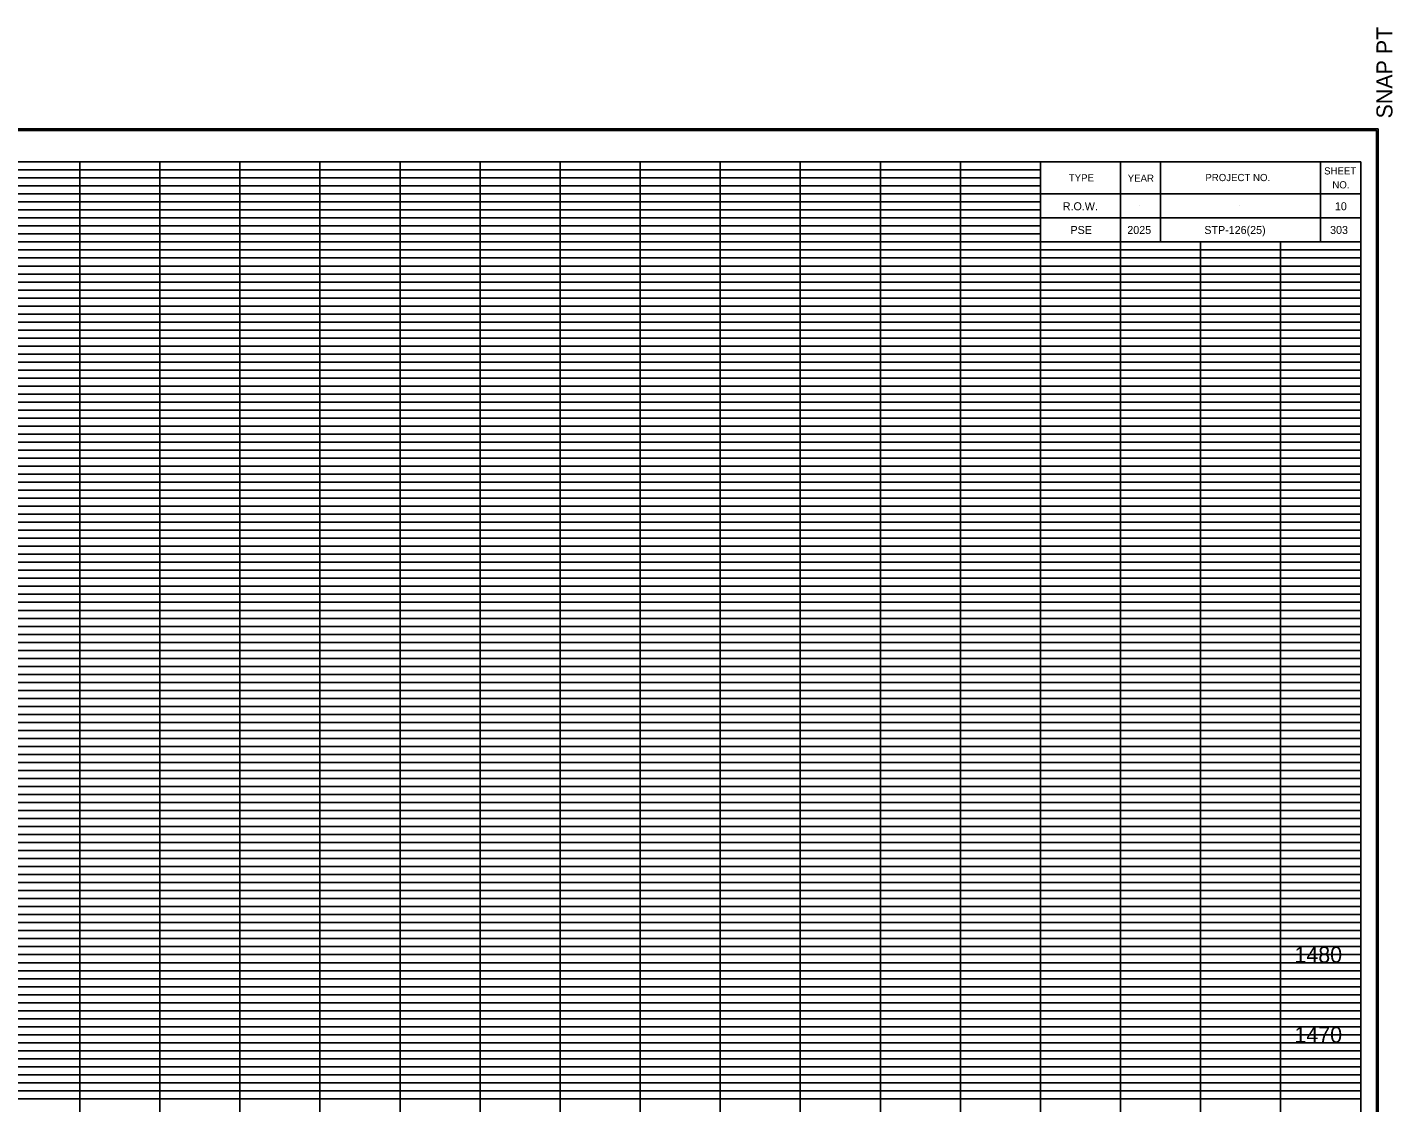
# Model space of a CAD drawing. Extents: x 980 to 2064, y 978 to 2267.
# Drawn here: x 1523.4 to 1694, y 2132.5 to 2266.8 of the extents above; entities that cross this region are included whole.
import ezdxf

# ---------------------------------------------------------------- set-up
doc = ezdxf.new("R2010")
doc.units = 0
for name, color, linetype in [('Default', 7, 'Continuous'), ('DESIGN - SCRATCH - User 1', 7, 'Continuous'), ('DESIGN - SHEET - Corner Text', 7, 'Continuous'), ('DESIGN - SHEET - Light Grid', 7, 'Continuous'), ('DESIGN - SHEET - Linework', 7, 'Continuous'), ('DESIGN - SHEET - Plot Shape', 7, 'Continuous')]:
    doc.layers.add(name, color=color, linetype=linetype)

# ---------------------------------------------------------------- blocks, each defined once
blk = doc.blocks.new('XSTSHT')
at = {"layer": 'DESIGN - SCRATCH - User 1'}
for p, q in [((28.5, 20.45), (28.5, 20.45)), ((29.24, 20.45), (29.24, 20.45)), ((30.49, 20.45), (30.49, 20.45)), ((31.74, 20.45), (31.74, 20.45)), ((28.5, 20.15), (28.5, 20.15)), ((29.24, 20.15), (29.24, 20.15)), ((30.49, 20.15), (30.49, 20.15)), ((31.74, 20.15), (31.74, 20.15))]:
    blk.add_line(p, q, dxfattribs=at)
at = {"layer": 'DESIGN - SHEET - Light Grid'}
for p, q in [((8, 20.9), (16, 20.9)), ((16, 20.9), (24, 20.9)), ((24, 20.9), (28, 20.9)), ((8, 20.8), (16, 20.8)), ((8, 20.7), (16, 20.7)), ((16, 20.8), (24, 20.8)), ((16, 20.7), (24, 20.7)), ((24, 20.8), (28, 20.8)), ((24, 20.7), (28, 20.7)), ((8, 20.6), (16, 20.6)), ((8, 20.5), (16, 20.5)), ((16, 20.6), (24, 20.6)), ((16, 20.5), (24, 20.5)), ((24, 20.6), (28, 20.6)), ((24, 20.5), (28, 20.5)), ((8, 20.4), (16, 20.4)), ((8, 20.3), (16, 20.3)), ((16, 20.4), (24, 20.4)), ((16, 20.3), (24, 20.3)), ((24, 20.4), (28, 20.4)), ((24, 20.3), (28, 20.3)), ((8, 20.2), (16, 20.2)), ((16, 20.2), (24, 20.2)), ((24, 20.2), (28, 20.2)), ((8, 20.1), (16, 20.1)), ((16, 20.1), (24, 20.1)), ((24, 20.1), (28, 20.1)), ((8, 19.9), (16, 19.9)), ((8, 19.8), (16, 19.8)), ((16, 19.9), (24, 19.9)), ((16, 19.8), (24, 19.8)), ((24, 19.9), (32, 19.9)), ((24, 19.8), (32, 19.8)), ((8, 19.7), (16, 19.7)), ((16, 19.7), (24, 19.7)), ((24, 19.7), (32, 19.7)), ((8, 19.6), (16, 19.6)), ((8, 19.5), (16, 19.5)), ((16, 19.6), (24, 19.6)), ((16, 19.5), (24, 19.5)), ((24, 19.6), (32, 19.6)), ((24, 19.5), (32, 19.5)), ((8, 19.4), (16, 19.4)), ((8, 19.3), (16, 19.3)), ((16, 19.4), (24, 19.4)), ((16, 19.3), (24, 19.3)), ((24, 19.4), (32, 19.4)), ((24, 19.3), (32, 19.3)), ((8, 19.2), (16, 19.2)), ((16, 19.2), (24, 19.2)), ((24, 19.2), (32, 19.2)), ((8, 19.1), (16, 19.1)), ((16, 19.1), (24, 19.1)), ((24, 19.1), (32, 19.1)), ((8, 18.9), (16, 18.9)), ((8, 18.8), (16, 18.8)), ((16, 18.9), (24, 18.9)), ((16, 18.8), (24, 18.8)), ((24, 18.9), (32, 18.9)), ((24, 18.8), (32, 18.8)), ((8, 18.7), (16, 18.7)), ((8, 18.6), (16, 18.6)), ((16, 18.7), (24, 18.7)), ((16, 18.6), (24, 18.6)), ((24, 18.7), (32, 18.7)), ((24, 18.6), (32, 18.6)), ((8, 18.5), (16, 18.5)), ((16, 18.5), (24, 18.5)), ((24, 18.5), (32, 18.5)), ((8, 18.4), (16, 18.4)), ((8, 18.3), (16, 18.3)), ((16, 18.4), (24, 18.4)), ((16, 18.3), (24, 18.3)), ((24, 18.4), (32, 18.4)), ((24, 18.3), (32, 18.3)), ((8, 18.2), (16, 18.2)), ((8, 18.1), (16, 18.1)), ((16, 18.2), (24, 18.2)), ((16, 18.1), (24, 18.1)), ((24, 18.2), (32, 18.2)), ((24, 18.1), (32, 18.1)), ((8, 17.9), (16, 17.9)), ((8, 17.8), (16, 17.8)), ((16, 17.9), (24, 17.9)), ((16, 17.8), (24, 17.8)), ((24, 17.9), (32, 17.9)), ((24, 17.8), (32, 17.8)), ((8, 17.7), (16, 17.7)), ((8, 17.6), (16, 17.6)), ((16, 17.7), (24, 17.7)), ((16, 17.6), (24, 17.6)), ((24, 17.7), (32, 17.7)), ((24, 17.6), (32, 17.6)), ((8, 17.5), (16, 17.5)), ((8, 17.4), (16, 17.4)), ((16, 17.5), (24, 17.5)), ((16, 17.4), (24, 17.4)), ((24, 17.5), (32, 17.5)), ((24, 17.4), (32, 17.4)), ((8, 17.3), (16, 17.3)), ((16, 17.3), (24, 17.3)), ((24, 17.3), (32, 17.3)), ((8, 17.2), (16, 17.2)), ((8, 17.1), (16, 17.1)), ((16, 17.2), (24, 17.2)), ((16, 17.1), (24, 17.1)), ((24, 17.2), (32, 17.2)), ((24, 17.1), (32, 17.1)), ((8, 16.9), (16, 16.9)), ((16, 16.9), (24, 16.9)), ((24, 16.9), (32, 16.9)), ((8, 16.8), (16, 16.8)), ((16, 16.8), (24, 16.8)), ((24, 16.8), (32, 16.8)), ((8, 16.7), (16, 16.7)), ((8, 16.6), (16, 16.6)), ((16, 16.7), (24, 16.7)), ((16, 16.6), (24, 16.6)), ((24, 16.7), (32, 16.7)), ((24, 16.6), (32, 16.6)), ((8, 16.5), (16, 16.5)), ((8, 16.4), (16, 16.4)), ((16, 16.5), (24, 16.5)), ((16, 16.4), (24, 16.4)), ((24, 16.5), (32, 16.5)), ((24, 16.4), (32, 16.4)), ((8, 16.3), (16, 16.3)), ((16, 16.3), (24, 16.3)), ((24, 16.3), (32, 16.3)), ((8, 16.2), (16, 16.2)), ((8, 16.1), (16, 16.1)), ((16, 16.2), (24, 16.2)), ((16, 16.1), (24, 16.1)), ((24, 16.2), (32, 16.2)), ((24, 16.1), (32, 16.1)), ((8, 15.9), (16, 15.9)), ((16, 15.9), (24, 15.9)), ((24, 15.9), (32, 15.9)), ((8, 15.8), (16, 15.8)), ((8, 15.7), (16, 15.7)), ((16, 15.8), (24, 15.8)), ((16, 15.7), (24, 15.7)), ((24, 15.8), (32, 15.8)), ((24, 15.7), (32, 15.7)), ((8, 15.6), (16, 15.6)), ((16, 15.6), (24, 15.6)), ((24, 15.6), (32, 15.6)), ((8, 15.5), (16, 15.5)), ((8, 15.4), (16, 15.4)), ((16, 15.5), (24, 15.5)), ((16, 15.4), (24, 15.4)), ((24, 15.5), (32, 15.5)), ((24, 15.4), (32, 15.4)), ((8, 15.3), (16, 15.3)), ((8, 15.2), (16, 15.2)), ((16, 15.3), (24, 15.3)), ((16, 15.2), (24, 15.2)), ((24, 15.3), (32, 15.3)), ((24, 15.2), (32, 15.2)), ((8, 15.1), (16, 15.1)), ((16, 15.1), (24, 15.1)), ((24, 15.1), (32, 15.1)), ((8, 14.9), (16, 14.9)), ((16, 14.9), (24, 14.9)), ((24, 14.9), (32, 14.9)), ((8, 14.8), (16, 14.8)), ((8, 14.7), (16, 14.7)), ((16, 14.8), (24, 14.8)), ((16, 14.7), (24, 14.7)), ((24, 14.8), (32, 14.8)), ((24, 14.7), (32, 14.7)), ((8, 14.6), (16, 14.6)), ((8, 14.5), (16, 14.5)), ((16, 14.6), (24, 14.6)), ((16, 14.5), (24, 14.5)), ((24, 14.6), (32, 14.6)), ((24, 14.5), (32, 14.5)), ((8, 14.4), (16, 14.4)), ((16, 14.4), (24, 14.4)), ((24, 14.4), (32, 14.4)), ((8, 14.3), (16, 14.3)), ((8, 14.2), (16, 14.2)), ((16, 14.3), (24, 14.3)), ((16, 14.2), (24, 14.2)), ((24, 14.3), (32, 14.3)), ((24, 14.2), (32, 14.2)), ((8, 14.1), (16, 14.1)), ((16, 14.1), (24, 14.1)), ((24, 14.1), (32, 14.1)), ((8, 13.9), (16, 13.9)), ((16, 13.9), (24, 13.9)), ((24, 13.9), (32, 13.9)), ((8, 13.8), (16, 13.8)), ((8, 13.7), (16, 13.7)), ((16, 13.8), (24, 13.8)), ((16, 13.7), (24, 13.7)), ((24, 13.8), (32, 13.8)), ((24, 13.7), (32, 13.7)), ((8, 13.6), (16, 13.6)), ((8, 13.5), (16, 13.5)), ((16, 13.6), (24, 13.6)), ((16, 13.5), (24, 13.5)), ((24, 13.6), (32, 13.6)), ((24, 13.5), (32, 13.5)), ((8, 13.4), (16, 13.4)), ((16, 13.4), (24, 13.4)), ((24, 13.4), (32, 13.4)), ((8, 13.3), (16, 13.3)), ((8, 13.2), (16, 13.2)), ((16, 13.3), (24, 13.3)), ((16, 13.2), (24, 13.2)), ((24, 13.3), (32, 13.3)), ((24, 13.2), (32, 13.2)), ((8, 13.1), (16, 13.1)), ((16, 13.1), (24, 13.1)), ((24, 13.1), (32, 13.1)), ((8, 12.9), (16, 12.9)), ((8, 12.8), (16, 12.8)), ((16, 12.9), (24, 12.9)), ((16, 12.8), (24, 12.8)), ((24, 12.9), (32, 12.9)), ((24, 12.8), (32, 12.8)), ((8, 12.7), (16, 12.7)), ((16, 12.7), (24, 12.7)), ((24, 12.7), (32, 12.7)), ((8, 12.6), (16, 12.6)), ((8, 12.5), (16, 12.5)), ((16, 12.6), (24, 12.6)), ((16, 12.5), (24, 12.5)), ((24, 12.6), (32, 12.6)), ((24, 12.5), (32, 12.5)), ((8, 12.4), (16, 12.4)), ((8, 12.3), (16, 12.3)), ((16, 12.4), (24, 12.4)), ((16, 12.3), (24, 12.3)), ((24, 12.4), (32, 12.4)), ((24, 12.3), (32, 12.3)), ((8, 12.2), (16, 12.2)), ((16, 12.2), (24, 12.2)), ((24, 12.2), (32, 12.2)), ((8, 12.1), (16, 12.1)), ((16, 12.1), (24, 12.1)), ((24, 12.1), (32, 12.1)), ((8, 11.9), (16, 11.9)), ((8, 11.8), (16, 11.8)), ((16, 11.9), (24, 11.9)), ((16, 11.8), (24, 11.8)), ((24, 11.9), (32, 11.9)), ((24, 11.8), (32, 11.8)), ((8, 11.7), (16, 11.7)), ((8, 11.6), (16, 11.6)), ((16, 11.7), (24, 11.7)), ((16, 11.6), (24, 11.6)), ((24, 11.7), (32, 11.7)), ((24, 11.6), (32, 11.6)), ((8, 11.5), (16, 11.5)), ((16, 11.5), (24, 11.5)), ((24, 11.5), (32, 11.5)), ((8, 11.4), (16, 11.4)), ((8, 11.3), (16, 11.3)), ((16, 11.4), (24, 11.4)), ((16, 11.3), (24, 11.3)), ((24, 11.4), (32, 11.4)), ((24, 11.3), (32, 11.3)), ((8, 11.2), (16, 11.2)), ((8, 11.1), (16, 11.1)), ((16, 11.2), (24, 11.2)), ((16, 11.1), (24, 11.1)), ((24, 11.2), (32, 11.2)), ((24, 11.1), (32, 11.1)), ((8, 10.9), (16, 10.9)), ((8, 10.8), (16, 10.8)), ((16, 10.9), (24, 10.9)), ((16, 10.8), (24, 10.8)), ((24, 10.9), (32, 10.9)), ((24, 10.8), (32, 10.8)), ((8, 10.7), (16, 10.7)), ((8, 10.6), (16, 10.6)), ((16, 10.7), (24, 10.7)), ((16, 10.6), (24, 10.6)), ((24, 10.7), (32, 10.7)), ((24, 10.6), (32, 10.6)), ((8, 10.5), (16, 10.5)), ((16, 10.5), (24, 10.5)), ((24, 10.5), (32, 10.5)), ((8, 10.4), (16, 10.4)), ((8, 10.3), (16, 10.3)), ((16, 10.4), (24, 10.4)), ((16, 10.3), (24, 10.3)), ((24, 10.4), (32, 10.4)), ((24, 10.3), (32, 10.3)), ((8, 10.2), (16, 10.2)), ((8, 10.1), (16, 10.1)), ((16, 10.2), (24, 10.2)), ((16, 10.1), (24, 10.1)), ((24, 10.2), (32, 10.2)), ((24, 10.1), (32, 10.1)), ((8, 9.9), (16, 9.9)), ((16, 9.9), (24, 9.9)), ((24, 9.9), (32, 9.9)), ((8, 9.8), (16, 9.8)), ((16, 9.8), (24, 9.8)), ((24, 9.8), (32, 9.8)), ((8, 9.7), (16, 9.7)), ((8, 9.6), (16, 9.6)), ((16, 9.7), (24, 9.7)), ((16, 9.6), (24, 9.6)), ((24, 9.7), (32, 9.7)), ((24, 9.6), (32, 9.6)), ((8, 9.5), (16, 9.5)), ((8, 9.4), (16, 9.4)), ((16, 9.5), (24, 9.5)), ((16, 9.4), (24, 9.4)), ((24, 9.5), (32, 9.5)), ((24, 9.4), (32, 9.4)), ((8, 9.3), (16, 9.3)), ((16, 9.3), (24, 9.3)), ((24, 9.3), (32, 9.3))]:
    blk.add_line(p, q, dxfattribs=at)
at = {"layer": 'DESIGN - SHEET - Linework'}
for p, q in [((-1.823, 21.414), (32.217, 21.414)), ((32.217, 21.414), (32.217, -0.414)), ((16, 0), (16, 21)), ((17, 0), (17, 21)), ((18, 0), (18, 21)), ((19, 0), (19, 21)), ((20, 0), (20, 21)), ((21, 0), (21, 21)), ((22, 0), (22, 21)), ((23, 0), (23, 21)), ((24, 0), (24, 21)), ((25, 0), (25, 21)), ((26, 0), (26, 21)), ((27, 0), (27, 21)), ((0, 20), (28, 20)), ((28, 0), (28, 20)), ((29, 0), (29, 20)), ((30, 0), (30, 20)), ((31, 0), (31, 20)), ((0, 19), (32, 19)), ((0, 18), (32, 18)), ((0, 17), (32, 17)), ((0, 16), (32, 16)), ((0, 15), (32, 15)), ((0, 14), (32, 14)), ((0, 13), (32, 13)), ((0, 12), (32, 12)), ((0, 11), (32, 11)), ((0, 10), (32, 10))]:
    blk.add_line(p, q, dxfattribs=at)
for points in [[(0, 21), (0, 0), (32, 0), (32, 21), (0, 21)], [(28, 21), (28, 20), (32, 20), (32, 21), (31.5, 21), (31.5, 20), (29.5, 20), (29.5, 21), (29, 21), (29, 20), (32, 20), (28, 20), (28, 20.3), (32, 20.3), (32, 20.6), (28, 20.6)]]:
    blk.add_lwpolyline(points, dxfattribs=at)
at = {"layer": 'DESIGN - SHEET - Plot Shape'}
for points in [[(-1.803, 21.394), (32.197, 21.394), (32.197, -0.394), (-1.803, -0.394)], [(-0.85, 21), (32, 21), (32, -0.25), (-0.85, -0.25)]]:
    blk.add_lwpolyline(points, close=True, dxfattribs=at)
at = {"layer": 'DESIGN - SHEET - Corner Text'}
blk.add_text('  SNAP PT', height=0.2, rotation=90, dxfattribs=at).set_placement((32.397, 21.394))
for s, p in [('TYPE', (28.354, 20.756)), ('YEAR', (29.09, 20.752)), ('PROJECT NO.', (30.06, 20.76)), ('SHEET', (31.543, 20.843)), ('NO.', (31.646, 20.669))]:
    blk.add_text(s, height=0.09, dxfattribs=at).set_placement(p)

msp = doc.modelspace()

# ---------------------------------------------------------------- block references
at = {"layer": 'Default', "xscale": 10, "yscale": 10}
msp.add_blockref('XSTSHT', (1370, 2040), dxfattribs=at)

# ---------------------------------------------------------------- texts
at = {"layer": 'Default'}
for s, p in [('     1480     ', (1678.01, 2150)), ('     1470     ', (1678.01, 2140))]:
    msp.add_text(s, height=2, dxfattribs=at).set_placement(p)
at = {"layer": 'DESIGN - SHEET - Corner Text'}
for s, p in [('R.O.W.', (1652.79, 2243.96)), ('10', (1686.78, 2243.96)), ('PSE', (1653.75, 2241)), ('2025', (1660.85, 2241)), ('STP-126(25)', (1670.47, 2241)), ('303', (1686.18, 2241))]:
    msp.add_text(s, height=1, dxfattribs=at).set_placement(p)

doc.saveas('drawing.dxf')
